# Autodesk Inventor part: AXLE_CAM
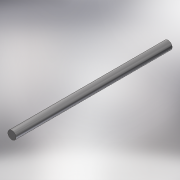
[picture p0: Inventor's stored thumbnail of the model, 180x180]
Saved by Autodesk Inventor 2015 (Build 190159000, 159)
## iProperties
Created: 2014-08
Part Number: AXLE_CAM
Material: Steel, Mild
Document SubType Name: Modeling
Designer: lakshayg
Density: 7.85 g/cm^3
Appearance: Semi-Polished
Mass: 202.954 g
Surface Area: 88.4421 cm^2
Volume: 25.8541 cm^3
Author: lakshayg
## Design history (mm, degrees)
sketch "Sketch1"
  geometry: C1 r 6 at (0, 0); 1 further point
  constraints: 1 centre point, 1 coincident
  dimensions: "d0" = 12 diameter of C1
extrude "Extrusion1" new body sketch "Sketch1" distance "d1" = 228.6; taper "d2" = 0 deg
body "Solid1"
